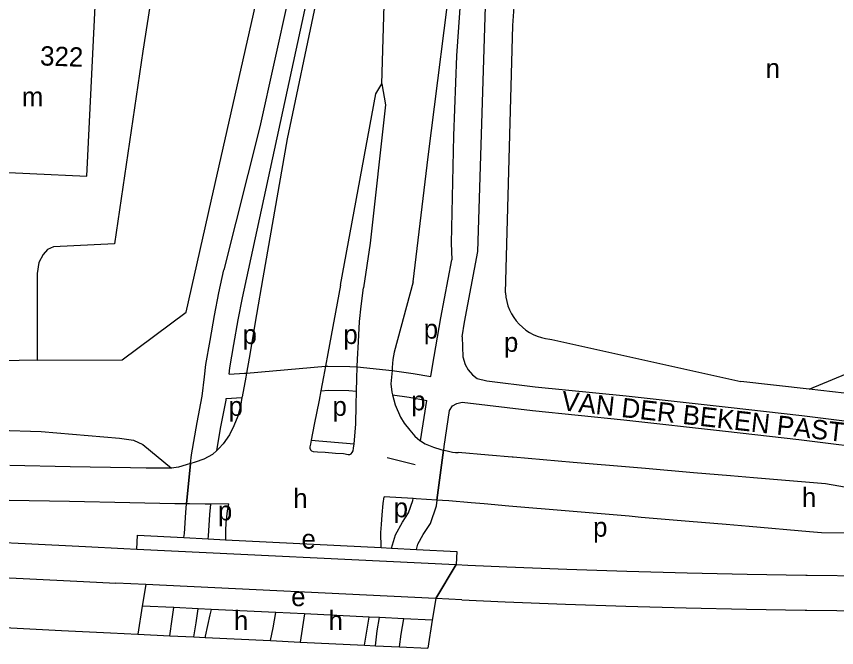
# Model space of a CAD drawing. Extents: x 161093 to 163177, y 379000 to 380904.
# Drawn here: x 161451 to 161621, y 379596.7 to 379727.5 of the extents above; entities that cross this region are included whole.
import ezdxf

# ---------------------------------------------------------------- set-up
doc = ezdxf.new("R2010")
doc.units = 0
for name, color, linetype in [('BLT_Basislijn', 7, 'Continuous'), ('BLT_Bebouwing', 7, 'Continuous'), ('BLT_Centroide', 7, 'Continuous'), ('BLT_Huisnummer', 7, 'Continuous'), ('BLT_Straatnaam_verkleind', 7, 'Continuous'), ('BLT_Vlakafsluiter', 7, 'Continuous')]:
    doc.layers.add(name, color=color, linetype=linetype)

msp = doc.modelspace()

# ---------------------------------------------------------------- linework, layer by layer
at = {"layer": 'BLT_Basislijn'}
for p, q in [((161518.74, 379783.05), (161501.53, 379704.6)), ((161553.92, 379725.65), (161555.8, 379751.1)), ((161552.42, 379670.22), (161553.92, 379725.65)), ((161615.34, 379650.24), (161686.42, 379679.79)), ((161562.05, 379660.58), (161601.19, 379651.85)), ((161615.34, 379650.24), (161601.19, 379651.85)), ((161625.61, 379649.08), (161615.34, 379650.24)), ((161512.16, 379639.74), (161521.08, 379638.96)), ((161533.69, 379634.57), (161527.92, 379636.02)), ((161476.14, 379620), (161485.75, 379619.51)), ((161485.75, 379619.51), (161490.76, 379619.26)), ((161490.76, 379619.26), (161494.37, 379619.08)), ((161494.37, 379619.08), (161526.63, 379617.45)), ((161476, 379617.16), (161542.12, 379613.95)), ((161526.63, 379617.45), (161528.8, 379617.34)), ((161528.8, 379617.34), (161533.95, 379617.08)), ((161533.95, 379617.08), (161542.31, 379616.65)), ((161542.12, 379613.95), (161542.18, 379613.94)), ((161477.84, 379609.81), (161471.66, 379610.11)), ((161477.84, 379609.81), (161477.13, 379605.34)), ((161537.9, 379606.89), (161477.84, 379609.81)), ((161537.96, 379606.89), (161537.25, 379602.42)), ((161537.96, 379606.89), (161537.9, 379606.89)), ((161543.36, 379606.63), (161537.96, 379606.89)), ((161477.13, 379605.34), (161476.21, 379599.52)), ((161483.68, 379605.02), (161477.13, 379605.34)), ((161488.7, 379604.77), (161483.68, 379605.02)), ((161491.41, 379604.64), (161488.7, 379604.77)), ((161504.81, 379603.99), (161491.41, 379604.64)), ((161510.77, 379603.7), (161504.81, 379603.99)), ((161524.17, 379603.05), (161510.77, 379603.7)), ((161526.31, 379602.95), (161524.17, 379603.05)), ((161531.34, 379602.7), (161526.31, 379602.95)), ((161537.25, 379602.42), (161531.34, 379602.7)), ((161537.25, 379602.42), (161536.33, 379596.59)), ((161470.55, 379599.8), (161476.21, 379599.52)), ((161476.21, 379599.52), (161482.83, 379599.2)), ((161482.83, 379599.2), (161487.85, 379598.96)), ((161487.85, 379598.96), (161490.16, 379598.84)), ((161490.16, 379598.84), (161503.72, 379598.18)), ((161503.72, 379598.18), (161509.86, 379597.88)), ((161509.86, 379597.88), (161523.19, 379597.23)), ((161523.19, 379597.23), (161525.45, 379597.12)), ((161525.45, 379597.12), (161530.46, 379596.88)), ((161530.46, 379596.88), (161536.33, 379596.59))]:
    msp.add_line(p, q, dxfattribs=at)
for points in [[(161488.3, 379790.29), (161486.64, 379753.46), (161482.53, 379753.86), (161477.22, 379720.29), (161471.35, 379680.39)], [(161455.37, 379656.3), (161472.95, 379656.33), (161486.26, 379666.23), (161491.43, 379689.22), (161505.18, 379750), (161512.95, 379786.11)], [(161495.14, 379653.36), (161495.28, 379654.68), (161496.1, 379659.5), (161497.02, 379664.64), (161497.9, 379669.23), (161520.53, 379773.49), (161521.69, 379773.24)], [(161521.69, 379773.24), (161520.98, 379757.67), (161517.98, 379743.34), (161513.02, 379730.07), (161507.19, 379702.12), (161502.15, 379673.31)], [(161526.81, 379713.54), (161527.57, 379739.24), (161530.47, 379769.11)], [(161546.71, 379678.82), (161548.57, 379738.44), (161549.22, 379746.79)], [(161533.29, 379672.54), (161536.36, 379698.44), (161541.68, 379740.45)], [(161541.68, 379740.45), (161543.69, 379740.16), (161542.27, 379719.34), (161541.65, 379702.77), (161541.15, 379680.49), (161541.3, 379677.1)], [(161518.21, 379671.84), (161525.55, 379711.44), (161526.81, 379713.54)], [(161526.81, 379713.54), (161527.54, 379709.18), (161524.4, 379680.49), (161522.99, 379671.27)], [(161501.53, 379704.6), (161494.03, 379674.97)], [(161471.35, 379680.39), (161458.76, 379679.75), (161457.5, 379679.2), (161456.57, 379678.19), (161455.72, 379676.52), (161455.31, 379674.22), (161455.37, 379656.3)], [(161543.41, 379661.1), (161543.94, 379664.17), (161546.71, 379678.82)], [(161536.92, 379652.88), (161537.29, 379655.02), (161539.02, 379665.06), (161541.3, 379677.1)], [(161487.16, 379634.87), (161487.34, 379636.66), (161488.5, 379643.38), (161489.57, 379648.79), (161490.05, 379652.81), (161490.33, 379655.36), (161491.17, 379660.35), (161492.1, 379665.55), (161493, 379670.23), (161494.03, 379674.97)], [(161502.15, 379673.31), (161500.8, 379665.76), (161499.29, 379656.68), (161498.74, 379653.61)], [(161518.21, 379671.84), (161515.59, 379657.63), (161515.09, 379655.02)], [(161533.29, 379672.54), (161529.35, 379657.91), (161529.04, 379656.43), (161528.95, 379654.77), (161528.9, 379654.14)], [(161521.7, 379654.88), (161521.75, 379656.49), (161521.93, 379660.08), (161522.18, 379664.27), (161522.51, 379667.47), (161522.99, 379671.27)], [(161552.42, 379670.22), (161552.51, 379669.32), (161552.68, 379668.43), (161552.93, 379667.56), (161553.26, 379666.72), (161553.65, 379665.9), (161554.12, 379665.13), (161554.66, 379664.4), (161555.26, 379663.72), (161555.91, 379663.09), (161556.62, 379662.53), (161557.38, 379662.03), (161558.17, 379661.6), (161559, 379661.24), (161559.86, 379660.95), (161560.74, 379660.74), (161561.64, 379660.61), (161562.05, 379660.58)], [(161543.41, 379661.1), (161543.58, 379656.98), (161544.04, 379655.38), (161544.67, 379654.3), (161545.55, 379653.27), (161546.57, 379652.45), (161548.53, 379651.99), (161558.56, 379650.79), (161577.45, 379648.89), (161598.58, 379646.57), (161613.83, 379644.81), (161631.56, 379642.59), (161657.22, 379639.82), (161686.97, 379636.4), (161714.22, 379633.26), (161733.73, 379631.1), (161746.36, 379629.63), (161755.31, 379628.82), (161762.24, 379629.08), (161769.08, 379629.98), (161777.69, 379631.61), (161789.34, 379634.73), (161822.91, 379643.33)], [(161455.37, 379656.3), (161331.45, 379654.01)], [(161515.09, 379655.02), (161514.67, 379652.85), (161514.15, 379649.94)], [(161515.09, 379655.02), (161515.58, 379655.06), (161520.15, 379655), (161521.7, 379654.88)], [(161521.56, 379649.88), (161521.63, 379652.44), (161521.7, 379654.88)], [(161495.14, 379653.36), (161498.31, 379653.57), (161498.74, 379653.61)], [(161498.74, 379653.61), (161498.59, 379652.76), (161497.83, 379648.7), (161497.8, 379648.53)], [(161528.9, 379654.14), (161528.68, 379651.36), (161528.84, 379649.64), (161528.99, 379649.08)], [(161528.9, 379654.14), (161533.26, 379653.55), (161536.92, 379652.88)], [(161256.79, 379649.21), (161268.61, 379648.52), (161286.79, 379647.95), (161334.43, 379647.41), (161384.55, 379645.12), (161417.14, 379642.88), (161438.53, 379642.04), (161456.14, 379641.47), (161472.44, 379640.15), (161475.32, 379639.71), (161477.25, 379638.79)], [(161514.15, 379649.94), (161513.8, 379648.02), (161512.79, 379642.97), (161512.16, 379639.74)], [(161514.15, 379649.94), (161515.73, 379650.06), (161519.92, 379650.01), (161521.56, 379649.88)], [(161521.08, 379638.96), (161521.39, 379643), (161521.48, 379646.95), (161521.56, 379649.88)], [(161497.8, 379648.53), (161497.47, 379646.74), (161496.93, 379644.69), (161496.11, 379642.66), (161495.23, 379640.78), (161493.93, 379638.94), (161492.97, 379637.95), (161492.58, 379637.59)], [(161492.58, 379637.59), (161493.42, 379642.48), (161494.51, 379648.01), (161494.55, 379648.31)], [(161494.55, 379648.31), (161497.8, 379648.53)], [(161528.99, 379649.08), (161532.47, 379648.61), (161536.09, 379647.95)], [(161528.99, 379649.08), (161529.53, 379647.01), (161530.68, 379644.45), (161531.44, 379643.22), (161532.57, 379641.76), (161533.61, 379640.57), (161534.69, 379639.63), (161534.82, 379639.55)], [(161534.82, 379639.55), (161536.09, 379647.95)], [(161540.83, 379645.85), (161541.44, 379646.81), (161542.32, 379647.33), (161543.43, 379647.57), (161558.02, 379645.82), (161576.93, 379643.92), (161598.02, 379641.6), (161613.23, 379639.84), (161630.98, 379637.62), (161656.67, 379634.85), (161686.4, 379631.43), (161713.66, 379628.29), (161733.17, 379626.14), (161745.84, 379624.66), (161755.18, 379623.81)], [(161539.61, 379637.66), (161539.7, 379638.42), (161540.83, 379645.85)], [(161512.16, 379639.74), (161511.97, 379638.86), (161511.87, 379638.36), (161511.89, 379638.05), (161512.01, 379637.73), (161512.2, 379637.52), (161512.58, 379637.35), (161513.43, 379637.3), (161515.06, 379637.2), (161517.15, 379637.04), (161518.87, 379636.92), (161519.82, 379636.76), (161520.12, 379636.77), (161520.42, 379636.9), (161520.65, 379637.15), (161520.81, 379637.51), (161520.91, 379638.07), (161521.08, 379638.96)], [(161534.82, 379639.55), (161535.76, 379638.95), (161537.52, 379638.26), (161538.99, 379637.77), (161539.56, 379637.66)], [(161492.58, 379637.59), (161491.67, 379636.77), (161489.92, 379635.75), (161488.11, 379635.14), (161487.21, 379634.88)], [(161539.56, 379637.66), (161539.61, 379637.66)], [(161539.61, 379637.66), (161540.3, 379637.52)], [(161628.66, 379628.95), (161618.77, 379630.63), (161616.28, 379630.84), (161603.83, 379631.91), (161599.03, 379632.32), (161591.37, 379632.97), (161581.41, 379633.83), (161578.92, 379634.04), (161566.46, 379635.1), (161554.01, 379636.17), (161553.78, 379636.19), (161548.89, 379636.61), (161542.61, 379637.14)], [(161483.22, 379633.92), (161483.18, 379633.92), (161477.93, 379633.9), (161474.69, 379633.96), (161462.19, 379634.21), (161449.69, 379634.47)], [(161487.16, 379634.87), (161486.24, 379634.6), (161484.61, 379634.09), (161483.22, 379633.92)], [(161487.21, 379634.88), (161487.16, 379634.87)], [(161486.32, 379626.53), (161483.91, 379626.53), (161474.54, 379626.71), (161462.05, 379626.97), (161449.55, 379627.22), (161437.05, 379627.47), (161432.05, 379627.57), (161424.57, 379628.62), (161412.1, 379630.37), (161407.12, 379631.07), (161399.62, 379631.22), (161387.12, 379631.48), (161374.62, 379631.73), (161370.84, 379631.8), (161362.13, 379631.98), (161349.63, 379632.23), (161337.13, 379632.48), (161324.63, 379632.73), (161312.14, 379632.99), (161304.06, 379633.15), (161299.64, 379633.24), (161289.98, 379633.43), (161287.14, 379633.49), (161285.02, 379633.53)], [(161526.63, 379617.45), (161526.6, 379620.57), (161526.69, 379622.25), (161526.84, 379624.26), (161527.09, 379626.58), (161527.28, 379627.97)], [(161533.27, 379627.61), (161527.28, 379627.97)], [(161528.8, 379617.34), (161529.64, 379620.08), (161531.07, 379622.71), (161532.32, 379624.64), (161533.22, 379627.24), (161533.27, 379627.61)], [(161538.22, 379627.3), (161533.93, 379627.57), (161533.27, 379627.61)], [(161533.95, 379617.08), (161534.27, 379618.14), (161535.37, 379620.15), (161536.85, 379622.43), (161538.11, 379626.09), (161538.27, 379627.3)], [(161538.27, 379627.3), (161538.22, 379627.3)], [(161553.14, 379626.06), (161547.99, 379626.49), (161545.33, 379626.72), (161540.66, 379627.12), (161539.39, 379627.23), (161538.27, 379627.3)], [(161485.75, 379619.51), (161485.86, 379620.34), (161486.14, 379624.75), (161486.32, 379626.53)], [(161486.37, 379626.53), (161486.32, 379626.53)], [(161491.34, 379626.47), (161490.15, 379626.47), (161486.94, 379626.53), (161486.37, 379626.53)], [(161490.76, 379619.26), (161490.84, 379619.83), (161491.12, 379624.34), (161491.34, 379626.47)], [(161494.98, 379626.5), (161491.34, 379626.47)], [(161494.98, 379626.5), (161494.76, 379625.06), (161494.42, 379622.6), (161494.37, 379620.96), (161494.37, 379619.08), (161494.37, 379619.08)], [(161746.67, 379611.27), (161746.7, 379612.27), (161740.2, 379612.82), (161738.77, 379612.95), (161727.74, 379613.89), (161715.29, 379614.95), (161702.83, 379616.02), (161694.81, 379616.7), (161690.38, 379617.08), (161677.92, 379618.15), (161665.47, 379619.21), (161653.01, 379620.28), (161640.48, 379620.36), (161627.94, 379620.45), (161617.91, 379620.52), (161615.42, 379620.73), (161602.96, 379621.8), (161598.16, 379622.21), (161590.51, 379622.86), (161580.54, 379623.71), (161578.05, 379623.93), (161565.6, 379624.99), (161553.14, 379626.06)], [(161476, 379617.16), (161476.14, 379620)], [(161447.03, 379618.57), (161452.86, 379618.28), (161465.34, 379617.67), (161473.28, 379617.29), (161476, 379617.16)], [(161542.31, 379616.65), (161542.18, 379613.94)], [(161542.18, 379613.94), (161544.61, 379613.83), (161552.7, 379613.46), (161565.15, 379612.97), (161577.6, 379612.55), (161590.06, 379612.21), (161602.52, 379611.94), (161614.67, 379611.74), (161614.98, 379611.74), (161627.44, 379611.61), (161639.9, 379611.55), (161652.36, 379611.57), (161664.82, 379611.66), (161669.47, 379611.71), (161677.33, 379611.79), (161689.86, 379611.87), (161702.4, 379611.86), (161714.94, 379611.79), (161727.48, 379611.64), (161740.02, 379611.42), (161746.67, 379611.27)], [(161238.61, 379611.1), (161248.14, 379610.64), (161256.91, 379610.21), (161260.62, 379610.03), (161273.11, 379609.42), (161285.59, 379608.81), (161298.08, 379608.21), (161310.56, 379607.6), (161323.05, 379606.99), (161335.53, 379606.38), (161346.62, 379605.84), (161348.02, 379605.77), (161360.51, 379605.16), (161372.99, 379604.55), (161385.48, 379603.95), (161397.96, 379603.34), (161410.45, 379602.73), (161422.93, 379602.12), (161435.42, 379601.51), (161447.9, 379600.9), (161448.56, 379600.87), (161460.39, 379600.29), (161470.55, 379599.8)], [(161446.65, 379611.33), (161452.47, 379611.04), (161464.96, 379610.43), (161471.66, 379610.11)], [(161482.83, 379599.2), (161483.34, 379602.62), (161483.68, 379605.02)], [(161543.36, 379606.63), (161552.36, 379606.22), (161564.85, 379605.73), (161577.35, 379605.31), (161589.85, 379604.96), (161602.35, 379604.69), (161614.54, 379604.49), (161614.85, 379604.49), (161627.35, 379604.36)], [(161487.85, 379598.96), (161488.29, 379601.89), (161488.7, 379604.77)], [(161491.41, 379604.64), (161491.15, 379603.49), (161490.19, 379599.07), (161490.16, 379598.84)], [(161503.72, 379598.18), (161504.26, 379600.81), (161504.81, 379603.99)], [(161510.77, 379603.7), (161509.86, 379597.88)], [(161523.19, 379597.23), (161524.17, 379603.05)], [(161525.45, 379597.12), (161525.84, 379600.23), (161526.31, 379602.95)], [(161530.46, 379596.88), (161530.78, 379599.5), (161531.34, 379602.7)]]:
    msp.add_lwpolyline(points, dxfattribs=at)
msp.add_arc((161542.78, 379645.38), 8.24, 252.4617, 268.8102, dxfattribs=at)
at = {"layer": 'BLT_Bebouwing'}
msp.add_lwpolyline([(161441.93, 379695.52), (161465.67, 379694.42), (161467.94, 379740.95), (161466.38, 379741.02)], dxfattribs=at)
at = {"layer": 'BLT_Vlakafsluiter'}
for p, q in [((161498.74, 379653.61), (161515.09, 379655.02)), ((161521.7, 379654.88), (161528.9, 379654.14)), ((161477.25, 379638.79), (161483.22, 379633.92)), ((161538.22, 379627.3), (161539.56, 379637.66)), ((161538.27, 379627.3), (161539.61, 379637.66)), ((161486.32, 379626.53), (161487.16, 379634.87)), ((161486.37, 379626.53), (161487.21, 379634.88)), ((161542.12, 379613.95), (161537.9, 379606.89)), ((161542.18, 379613.94), (161537.96, 379606.89))]:
    msp.add_line(p, q, dxfattribs=at)

# ---------------------------------------------------------------- texts
at = {"layer": 'BLT_Centroide'}
for s, p in [('n', (161606.34, 379714.74)), ('m', (161452.16, 379708.86)), ('p', (161535.48, 379660.74)), ('p', (161497.92, 379659.63)), ('p', (161518.82, 379659.63)), ('p', (161552.1, 379658.01)), ('p', (161495.01, 379644.74)), ('p', (161516.56, 379644.74)), ('p', (161532.87, 379645.88)), ('h', (161508.42, 379625.66)), ('h', (161613.86, 379625.86)), ('p', (161492.8, 379623.08)), ('p', (161529.24, 379623.73)), ('p', (161570.58, 379619.71)), ('e', (161510.13, 379617.23)), ('e', (161508, 379605.32)), ('h', (161496.12, 379600.35)), ('h', (161515.74, 379600.35))]:
    msp.add_text(s, height=4, dxfattribs=at).set_placement(p)
at = {"layer": 'BLT_Huisnummer'}
msp.add_text('322', height=4, rotation=358, dxfattribs=at).set_placement((161455.9, 379717.36))
at = {"layer": 'BLT_Straatnaam_verkleind'}
msp.add_text('VAN DER BEKEN PASTEELWEG', height=3.9999, rotation=353.5595, dxfattribs=at).set_placement((161563.88, 379645.93))

doc.saveas('drawing.dxf')
